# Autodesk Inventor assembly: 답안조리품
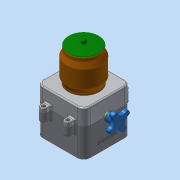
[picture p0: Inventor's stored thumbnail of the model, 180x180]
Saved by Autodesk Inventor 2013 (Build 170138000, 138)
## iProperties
Created: 2018-01
Part Number: 답안조리품
Document SubType Name: Assembly
Designer: dgall
Author: dgall
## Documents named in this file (9)
- C:\Users\dgall\Desktop\480107V1048\답안조리품.iam
- C:\Users\dgall\Desktop\480107V1048\본체.ipt
- C:\Users\dgall\Desktop\480107V1048\볼트 M4x12.ipt
- C:\Users\dgall\Desktop\480107V1048\본체커버.ipt
- C:\Users\dgall\Desktop\480107V1048\용기.ipt
- C:\Users\dgall\Desktop\480107V1048\용기캡.ipt
- C:\Users\dgall\Desktop\480107V1048\핸들.ipt
- C:\Users\dgall\Desktop\480107V1048\핸들축.ipt
- C:\Users\dgall\Desktop\480107V1048\볼트 M3x12.ipt
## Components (2 placed, 2 different names)
1. 핸들:1
2. 핸들축:1
